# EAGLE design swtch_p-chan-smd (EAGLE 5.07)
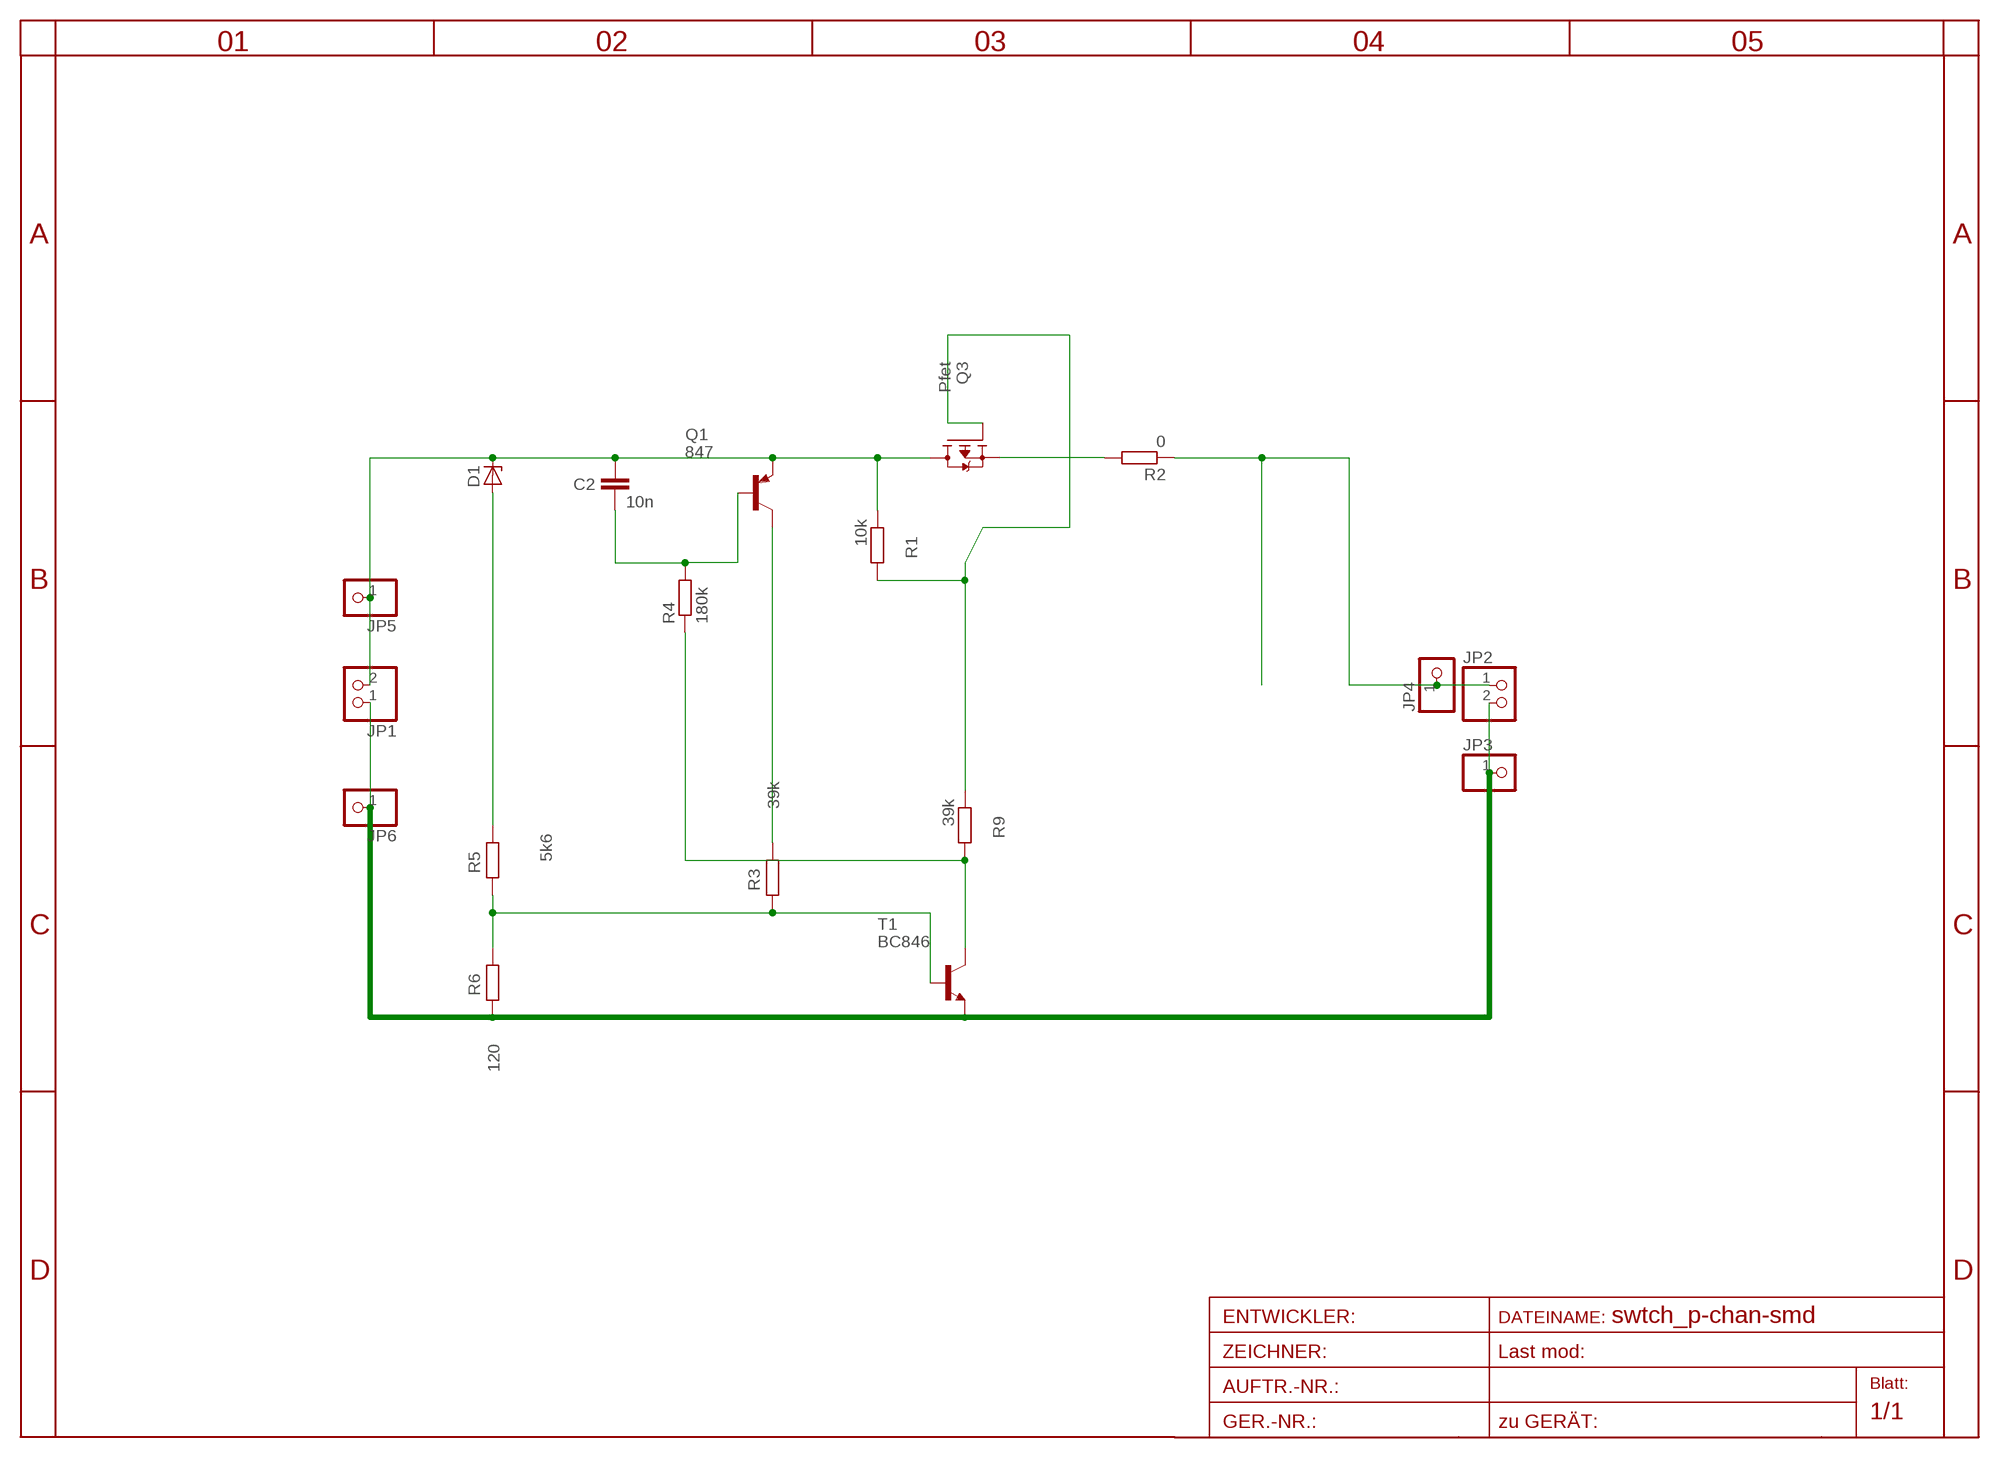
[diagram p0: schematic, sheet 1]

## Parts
C2  10n  C-EUC1206  [C1206]
D1  ZENER-DIODESOD80C  [SOD80C]
JP1  PINHD-1X2  [1X02]
JP2  PINHD-1X2  [1X02]
JP3  PINHD-1X11MM6  [1X1MM8]
JP4  PINHD-1X11MM6  [1X1MM8]
JP5  PINHD-1X11MM6  [1X1MM8]
JP6  PINHD-1X11MM6  [1X1MM8]
Q1  847  BC807-40SMD  [SOT23-BEC]
Q3  Pfet  FDD4141TO252  [TO252]
R1  10k  R-EU_R1206  [R1206]
R2  0  R-EU_0204/5  [0204/5]
R3  39k  R-EU_R1206  [R1206]
R4  180k  R-EU_R0805  [R0805]
R5  5k6  R-EU_R1206  [R1206]
R6  120  R-EU_R1206  [R1206]
R9  39k  R-EU_R1206  [R1206]
T1  BC846  [SOT23]

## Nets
B-Q1: C2.2 Q1.B R4.2
D: Q3.3(S) R2.2
GATE: Q3.1(G) R1.2 R9.1
N$1: D1.A R5.1
N$2: R4.1 R9.2 T1.3(C)
N$3: R3.2 R5.2 R6.1 T1.1(B)
N$4: Q1.C R3.1
V+IN: C2.1 D1.C JP1.2 JP5.1 Q1.E Q3.2(D) R1.1
V+OUT: JP2.1 JP4.1 R2.1
V-: JP1.1 JP2.2 JP3.1 JP6.1 R6.2 T1.2(E)

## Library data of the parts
C2 = rcl-2:C-EU: CAPACITOR, European symbol
D1 = diode-1:ZENER-DIODE: Z-Diode
JP1 JP2 = pinhead:PINHD-1X2: PIN HEADER
JP3-JP6 = pinhead:PINHD-1X1: PIN HEADER
Q1 = transistor-pnp:BC807*: PNP Transistror
Q3 = transistor-fet:FDD4141: P-Channel PowerTrench® MOSFET Source: FDD4141.pdf
R1-R6 R9 = rcl-2:R-EU_: RESISTOR, European symbol
T1 = transistor:BC846: NPN TRANSISTOR

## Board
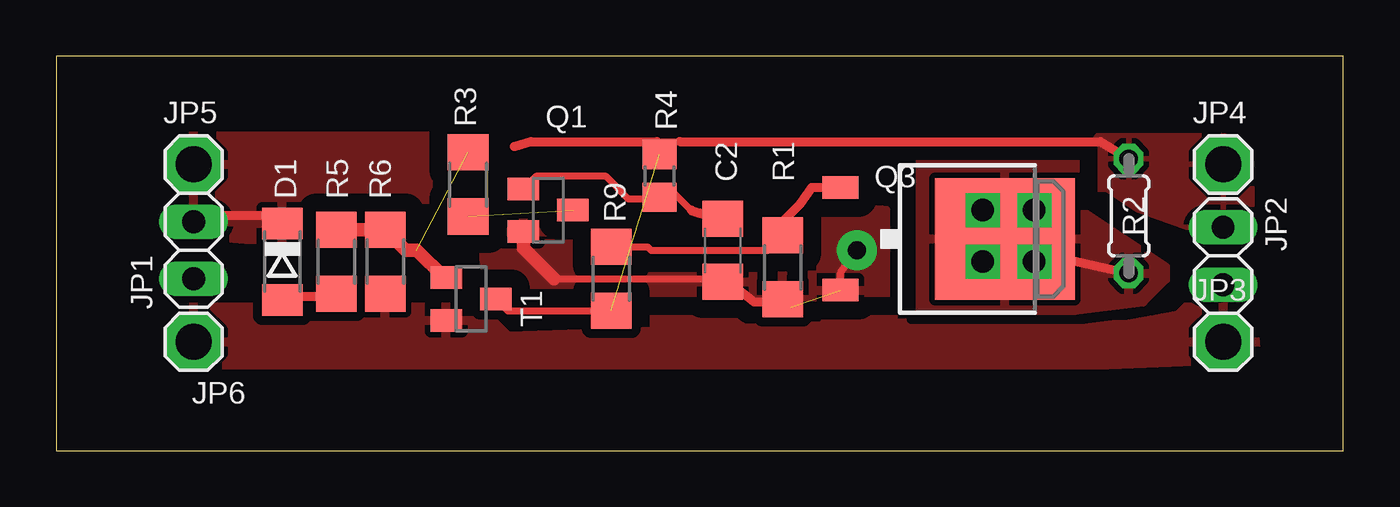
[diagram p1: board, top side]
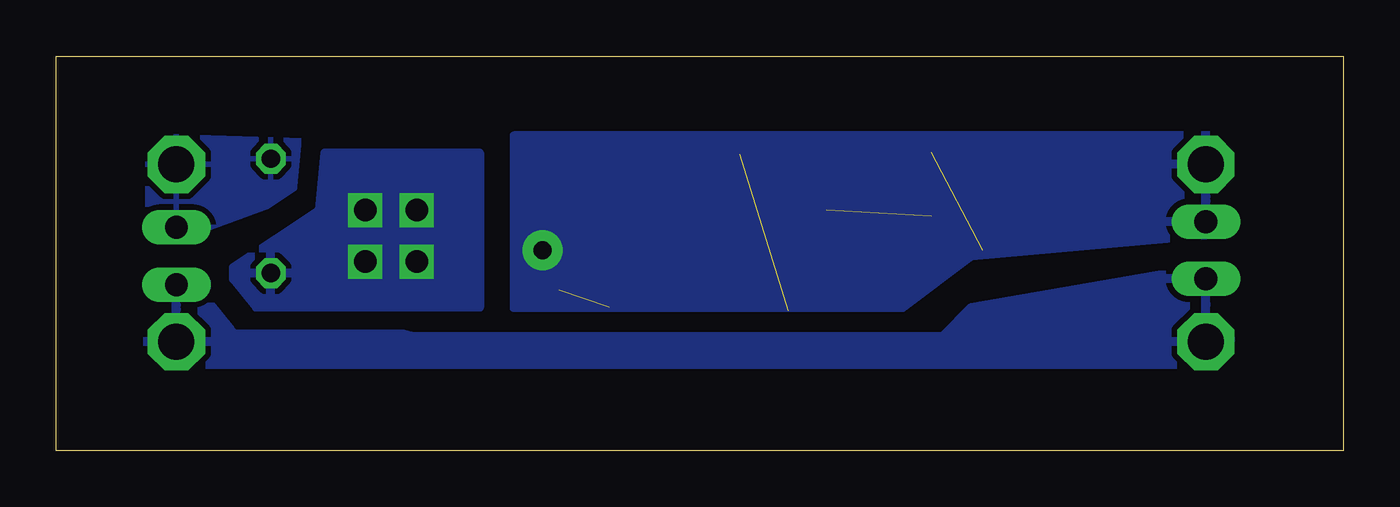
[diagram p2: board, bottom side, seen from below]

Size 57.15 x 17.5 mm. Coordinates in mm from the lower left corner, seen from the top.
Outline: 0,0 57.15,0 57.15,17.5 0,17.5 0,0
Copper layers (1*16): Top 0.035mm / dielectric 1.5mm / Bottom 0.035mm
Design rules "default": minimum track width 10mil, minimum drill 24mil, track to track 8mil, track to pad 8mil, pad to pad 8mil, via to via 8mil, smd to smd 8mil, copper to edge 40mil, drill to drill 8mil, minimum pad ring 10mil, minimum via ring 8mil, stop-mask expansion 4mil, vias tented up to drill 0mil, thermal gap 10mil

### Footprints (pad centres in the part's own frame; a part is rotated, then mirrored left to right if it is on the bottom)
C1206 = smd 1.6 x 1.8: 1 -1.4,0; 2 1.4,0
SOD80C = smd 1.4 x 1.8: A 1.7,0; C -1.7,0
1X02 = drill 1.016 long: 1 -1.27,0; 2 1.27,0
1X1MM8 = drill 1.6 pad 2.54 octagon: 1 0,0
SOT23-BEC = smd 1 x 1.4: B -0.95,-1.1; C 0,1.1; E 0.95,-1.1
TO252 = smd 1 x 1.6: 1 -2.28,-4.8; 2 2.28,-4.8 | smd 5.4 x 6.2: 3 0,2.5
R1206 = smd 1.6 x 1.803: 1 -1.422,0; 2 1.422,0
0204/5 = drill 0.813 octagon: 1 -2.54,0; 2 2.54,0
R0805 = smd 1.3 x 1.5: 1 -0.95,0; 2 0.95,0
SOT23 = smd 1 x 1.4: 1 -0.95,-1.1; 2 0.95,-1.1; 3 0,1.1

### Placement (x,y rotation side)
C2  29.59,8.89 90 top
D1  10.03,8.38 270 top
JP1  6.1,8.89 90 top
JP2  51.82,8.64 270 top
JP3  51.82,4.83 0 top
JP4  51.82,12.7 0 top
JP5  6.1,12.7 0 top
JP6  6.1,4.83 0 top
Q1  21.84,10.67 270 top
Q3  39.62,9.4 270 top
R1  32.26,8.13 90 top
R2  47.62,10.41 270 top
R3  18.29,11.81 90 top
R4  26.79,12.19 270 top
R5  12.45,8.38 90 top
R6  14.61,8.38 270 top
R9  24.64,7.62 270 top
T1  18.41,6.73 270 top

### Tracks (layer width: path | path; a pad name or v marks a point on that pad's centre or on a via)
B-Q1
  Top 0.305: 28.19,10.67 27.43,11.43 26.98,11.43 R4.2 26.72,11.18 25.4,11.18 24.38,12.19 21.34,12.19 20.76,11.62 Q1.B
  Top 0.406: C2.2 28.58,10.54 28.19,10.67
D  (via drill 1)
  Top 0.406: R2.2 44.2,8.64 43.18,9.65 42.38,9.65 Q3.3
  other vias: 43.43,10.67 41.15,10.67 41.15,8.38 43.43,8.38
  pour Bottom: 38.35,13.21 38.35,6.35 48.26,6.35 49.28,7.62 49.28,8.13 45.47,10.67 45.21,13.21
  pour Top (isolate 0.61): 38.35,13.21 38.35,6.22 45.21,6.22 48.26,6.6 49.28,7.62 49.28,8.13 45.47,10.67 45.21,13.21
GATE
  Top 0.305: R9.1 26.26,9.04 26.42,8.89 31.6,8.89 R1.2
  Top 0.406: R1.2 32.26,10.16 33.02,10.92 33.55,11.68 Q3.1
N$1
  Top 0.406: D1.A 10.49,6.94 10.67,6.86 11.84,6.86 R5.1
N$2  (1 unrouted)
  Top 0.305: R9.2 20.05,6.2 T1.3
N$3  (1 unrouted)
  Top 0.61: T1.1 17.21,7.68 16,8.89 15.52,8.89 R6.1 R5.2
N$4  (1 unrouted)
V+IN  (via drill 0.8 pad 1.78)  (1 unrouted)
  Top 0.305: 22.1,7.62 29.46,7.62 C2.1 | Q3.2 34.82,7.9 v35.56,8.89
  Top 0.406: C2.1 29.85,7.49 30.99,6.6 32.16,6.6 R1.1 32.61,6.36 | JP1.2 6.6,10.41 9.96,10.41 D1.C
  Top 0.61: Q1.E 20.74,8.97 22.1,7.62
  Bottom 0.305: v35.56,8.89 35.05,9.14
  pour Bottom (isolate 0.813, rank 5): 5.33,9.65 5.33,13.97 36.83,13.97 36.83,6.35 19.56,6.35 16.51,8.64
  pour Top (isolate 0.813, rank 5): 5.08,9.65 5.08,13.97 18.29,13.97 36.83,10.67 36.83,6.4 19.56,6.4 16.51,8.64
V+OUT
  Top 0.305: 26.67,13.26 26.67,13.72 27.69,13.72
  Top 0.406: 20.34,13.49 21.08,13.72 26.67,13.72 | R2.1 46.35,13.72 27.69,13.72
  pour Bottom (isolate 0.813, rank 5): 44.96,13.21 44.7,13.72 53.09,13.97 53.09,8.89 45.47,11.68
  pour Top (isolate 0.813, rank 5): 45.72,13.21 46.23,13.97 53.09,13.97 53.09,8.89 45.97,11.43
V-
  pour Bottom (isolate 0.813, rank 4): 4.83,8.38 5.08,3.81 53.09,3.81 53.09,8.13 45.47,6.35 41.4,5.08 17.78,5.08 16.51,6.35
  pour Top (isolate 0.813, rank 4): 5.08,6.35 5.08,3.81 44.45,3.81 50.8,4.83 50.8,6.6 45.47,6.35 40.89,5.8 17.78,5.8 16.51,6.35
  pour Top (isolate 0.406, rank 4): 7.37,6.35 7.37,3.81 46.74,3.81 53.34,4.06 53.09,6.6 47.5,5.59 43.18,5.84 20.07,5.08 18.8,6.35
